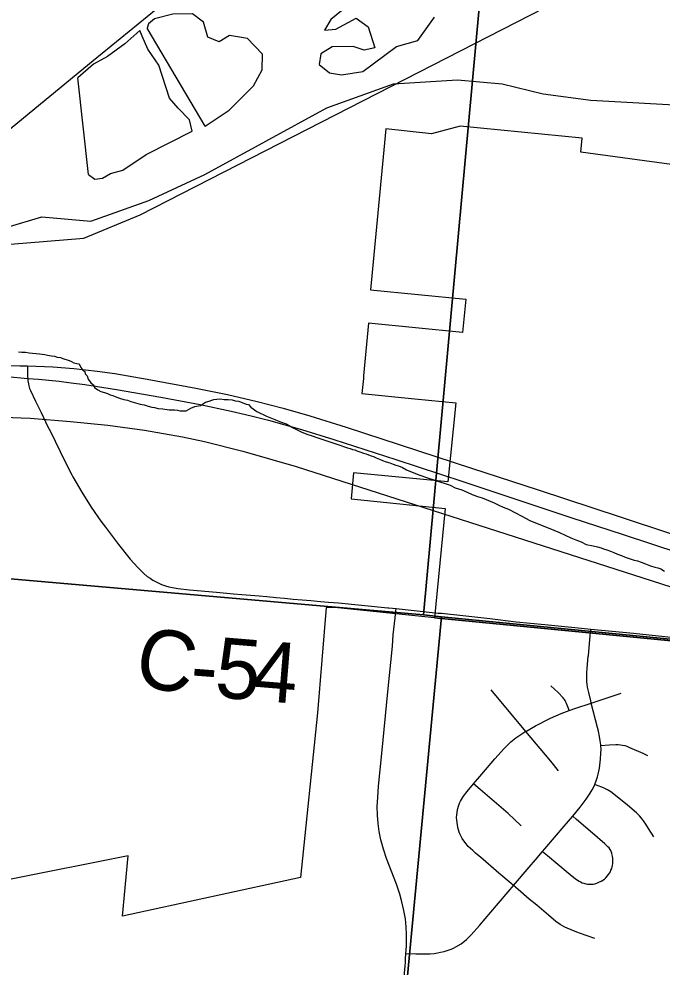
# Model space of a CAD drawing. Extents: x -1.4 to 35.4, y 0 to 22.
# Drawn here: x 25.196 to 25.802, y 15.521 to 16.414 of the extents above; entities that cross this region are included whole.
import ezdxf

# ---------------------------------------------------------------- set-up
doc = ezdxf.new("R2010")
doc.units = 0
for name, color, linetype in [('GM_X_County_Road', 7, 'Continuous'), ('GM_X_County_Road_Text', 7, 'Continuous'), ('GM_X_County_Text', 7, 'Continuous'), ('GM_X_Minor_Lake', 7, 'Continuous'), ('GM_X_Minor_River', 7, 'Continuous'), ('GM_X_Rail_Line', 7, 'Continuous'), ('GM_X_Section', 7, 'Continuous'), ('GM_X_State_Route', 7, 'Continuous'), ('GM_X_Township_Road', 7, 'Continuous')]:
    doc.layers.add(name, color=color, linetype=linetype)

msp = doc.modelspace()

# ---------------------------------------------------------------- linework, layer by layer
at = {"layer": 'GM_X_County_Road'}
for points in [[(25.20365, 16.08697), (25.20355, 16.08397), (25.20368, 16.07689), (25.20383, 16.07532)], [(25.20383, 16.07532), (25.20405, 16.07298), (25.20449, 16.07018), (25.20485, 16.06832), (25.2056, 16.06584), (25.20644, 16.06373), (25.2111, 16.05368), (25.21637, 16.04313), (25.22295, 16.02972), (25.22521, 16.0251)], [(25.22521, 16.0251), (25.23875, 15.99734), (25.2455, 15.9843)], [(25.2455, 15.9843), (25.24644, 15.98248), (25.25474, 15.96796), (25.26368, 15.95383), (25.2729, 15.94062), (25.27715, 15.93496)], [(25.27715, 15.93496), (25.28928, 15.91878), (25.30054, 15.90477), (25.30749, 15.8969), (25.31327, 15.89139), (25.31653, 15.8887), (25.3191, 15.88692), (25.32168, 15.88523), (25.32431, 15.88374), (25.32665, 15.88256), (25.32982, 15.88111), (25.33367, 15.87976), (25.33678, 15.87887), (25.34026, 15.87808), (25.34521, 15.87726), (25.35628, 15.87606), (25.38167, 15.87388), (25.39774, 15.87235), (25.40577, 15.87163), (25.4138, 15.87091), (25.42183, 15.87022), (25.42925, 15.86958), (25.43789, 15.86882), (25.44593, 15.86809), (25.45395, 15.86736), (25.4626, 15.86659), (25.47064, 15.8659), (25.47991, 15.86509), (25.48733, 15.86444), (25.4966, 15.86362), (25.54329, 15.85908)], [(25.54329, 15.85908), (25.5442, 15.85899), (25.55111, 15.85827)], [(25.55015, 15.84956), (25.55089, 15.85633), (25.55111, 15.85827)], [(25.55111, 15.85827), (25.59054, 15.85417), (25.59364, 15.85395), (25.61403, 15.85177), (25.63934, 15.84887), (25.66401, 15.84599), (25.69118, 15.8432), (25.72583, 15.83994), (25.73446, 15.83909)], [(25.5603, 15.53339), (25.56075, 15.54036), (25.56094, 15.55096), (25.56059, 15.55847), (25.55972, 15.56593), (25.55837, 15.57394), (25.55656, 15.58186), (25.55452, 15.58906), (25.55133, 15.59851), (25.54206, 15.62288), (25.53909, 15.63165), (25.5366, 15.64056), (25.53502, 15.64841), (25.53402, 15.65573), (25.53343, 15.66371), (25.53331, 15.67172), (25.53364, 15.68036), (25.5345, 15.69085), (25.53763, 15.72171), (25.54323, 15.77978), (25.54761, 15.82301), (25.54838, 15.83355), (25.55015, 15.84956)], [(25.73446, 15.83909), (25.77464, 15.8351), (25.80428, 15.83198), (25.82588, 15.8295), (25.84452, 15.82697), (25.84979, 15.82617), (25.86218, 15.82412), (25.8673, 15.82321), (25.87379, 15.82181), (25.87954, 15.82049), (25.88586, 15.81897), (25.89318, 15.81688)], [(25.53885, 15.29831), (25.54078, 15.31999), (25.54339, 15.34971), (25.54541, 15.37073), (25.55388, 15.46045), (25.55969, 15.52173), (25.55975, 15.52483), (25.55995, 15.52793), (25.5603, 15.53339)]]:
    msp.add_lwpolyline(points, dxfattribs=at)
at = {"layer": 'GM_X_County_Text'}
for points in [[(25.94903, 16.25792), (25.72505, 16.28855), (25.72628, 16.30175), (25.61133, 16.31284), (25.58444, 16.30585), (25.54144, 16.31044), (25.52704, 16.15887), (25.61682, 16.14984), (25.61374, 16.11863), (25.52506, 16.12738), (25.52196, 16.09419), (25.52042, 16.0776), (25.5202, 16.0753), (25.51887, 16.06103), (25.56873, 16.05608), (25.60721, 16.05228), (25.59985, 15.97784), (25.51077, 15.98632), (25.50853, 15.96168), (25.59738, 15.95277), (25.58718, 15.84949), (25.73939, 15.83491), (26.13662, 15.79613)], [(26.45501, 15.55992), (26.09418, 15.5213), (26.1119, 15.7121), (26.12869, 15.71539), (26.13662, 15.79613), (25.73939, 15.83491), (25.58719, 15.84949), (25.49604, 15.85897), (25.48524, 15.85929), (25.47708, 15.76014), (25.46096, 15.60505), (25.29309, 15.56851), (25.29849, 15.62549), (25.07154, 15.58016)]]:
    msp.add_lwpolyline(points, dxfattribs=at)
at = {"layer": 'GM_X_Minor_Lake'}
for points in [[(25.37105, 16.31291), (25.39374, 16.32803), (25.41658, 16.35112), (25.42485, 16.36615), (25.42515, 16.38095), (25.41103, 16.39568), (25.39401, 16.3983), (25.38441, 16.39242), (25.3735, 16.39682), (25.36961, 16.41095), (25.35914, 16.41876), (25.34055, 16.41838), (25.32339, 16.41417), (25.3176, 16.40934), (25.31638, 16.40519)], [(25.49956, 16.42161), (25.48954, 16.41346), (25.48364, 16.40332), (25.49428, 16.40425), (25.51346, 16.41487), (25.52468, 16.40667), (25.53111, 16.38678), (25.52082, 16.38471), (25.51065, 16.38796), (25.49091, 16.3876), (25.48016, 16.38098), (25.47844, 16.37114), (25.48815, 16.36334), (25.49949, 16.36121), (25.51966, 16.3646), (25.55124, 16.3879), (25.57146, 16.39356), (25.58707, 16.41566)], [(25.37105, 16.31291), (25.31638, 16.40519)], [(25.26126, 16.26728), (25.26724, 16.26298), (25.27447, 16.26397), (25.28176, 16.26838), (25.29359, 16.27156), (25.31551, 16.28631), (25.35882, 16.30823), (25.35638, 16.31891), (25.34559, 16.32977), (25.33744, 16.33943), (25.32744, 16.3704), (25.31712, 16.38542), (25.31168, 16.39769), (25.30951, 16.40305), (25.29522, 16.39042), (25.27905, 16.3786), (25.266, 16.37126), (25.25096, 16.35865)], [(25.26126, 16.26728), (25.25096, 16.35865)]]:
    msp.add_lwpolyline(points, dxfattribs=at)
at = {"layer": 'GM_X_Minor_River'}
for points in [[(25.18363, 16.21757), (25.21721, 16.22752), (25.26341, 16.22355), (25.31805, 16.24296), (25.37089, 16.26734), (25.48559, 16.33035), (25.54864, 16.353), (25.60903, 16.35671), (25.65106, 16.35282), (25.68956, 16.3433), (25.73459, 16.33745), (25.83046, 16.33208), (25.84447, 16.33066), (25.9464, 16.32516), (26.00204, 16.31871), (26.05844, 16.31262), (26.15296, 16.29664), (26.18177, 16.29567), (26.2226, 16.28876), (26.33585, 16.27999), (26.3975, 16.27075), (26.46407, 16.26103)], [(25.19523, 16.10041), (25.19826, 16.09998), (25.20167, 16.09992), (25.20508, 16.09949), (25.20849, 16.09905), (25.2119, 16.09862), (25.21494, 16.09857), (25.21759, 16.09815), (25.21986, 16.09773), (25.22251, 16.09731), (25.22629, 16.09648), (25.22894, 16.09606), (25.23159, 16.09526), (25.23462, 16.09483), (25.23689, 16.09403), (25.23877, 16.09324), (25.24104, 16.09283), (25.24293, 16.09204), (25.24519, 16.09124), (25.24745, 16.09006), (25.2501, 16.08926), (25.25237, 16.08884), (25.25383, 16.0854), (25.25569, 16.08309), (25.25757, 16.08192), (25.25792, 16.07964), (25.25978, 16.07771), (25.26087, 16.07465), (25.26347, 16.07119), (25.26572, 16.06925), (25.26682, 16.06657), (25.26983, 16.06463), (25.27284, 16.06306), (25.27623, 16.06186)], [(25.27623, 16.06186), (25.27888, 16.06106), (25.28152, 16.05988), (25.28416, 16.05907), (25.2868, 16.05789), (25.29133, 16.0563), (25.29436, 16.05549), (25.29776, 16.05467), (25.30116, 16.05348), (25.30531, 16.05227), (25.30985, 16.05106), (25.31363, 16.05024), (25.31741, 16.04904), (25.32081, 16.04822), (25.32347, 16.0478), (25.32687, 16.04698), (25.33104, 16.04654), (25.3371, 16.04568), (25.34013, 16.04563), (25.34203, 16.0456), (25.34506, 16.04517), (25.34733, 16.04475), (25.35037, 16.0447), (25.35303, 16.04466), (25.35762, 16.04724), (25.36144, 16.0487), (25.36487, 16.04941), (25.36677, 16.04976), (25.37138, 16.05272), (25.37481, 16.05381), (25.37749, 16.0549), (25.37939, 16.05525), (25.38205, 16.05559), (25.38547, 16.05591), (25.38888, 16.05548), (25.39268, 16.05541), (25.39647, 16.05498), (25.39949, 16.05417), (25.40252, 16.05374), (25.40441, 16.05333), (25.40969, 16.05096), (25.41196, 16.05054), (25.4142, 16.04823), (25.41983, 16.04396), (25.42887, 16.03963), (25.43679, 16.03646), (25.44283, 16.03409), (25.44736, 16.03249), (25.45037, 16.03092), (25.45338, 16.02898), (25.45715, 16.02702), (25.46167, 16.02504), (25.46695, 16.02268), (25.47186, 16.02108), (25.47639, 16.01948), (25.48772, 16.01588), (25.49225, 16.01429), (25.49603, 16.01309), (25.49904, 16.0119), (25.50244, 16.0107), (25.50508, 16.0099), (25.50773, 16.0091), (25.51, 16.0083), (25.51227, 16.00788), (25.51415, 16.00709), (25.51604, 16.0063), (25.51793, 16.00589), (25.52019, 16.00471), (25.52284, 16.00429), (25.5251, 16.00312), (25.52736, 16.00232), (25.52963, 16.00152), (25.53227, 16.00034), (25.53529, 15.99915), (25.5383, 15.99796), (25.5417, 15.99677), (25.5451, 15.99557), (25.54812, 15.99438), (25.55076, 15.99358), (25.55341, 15.99278), (25.55718, 15.9912), (25.56094, 15.98923), (25.56622, 15.98687), (25.57339, 15.98409), (25.58056, 15.9817), (25.58661, 15.9797), (25.59227, 15.97771), (25.59718, 15.97611), (25.60209, 15.97451), (25.60661, 15.97216), (25.61303, 15.97015), (25.61793, 15.96817), (25.62283, 15.96581), (25.62773, 15.96383), (25.63227, 15.96262), (25.63604, 15.96104), (25.63981, 15.95946), (25.64358, 15.95788), (25.64773, 15.95591), (25.65187, 15.95394), (25.65678, 15.95196)], [(25.65678, 15.95196), (25.66356, 15.94843), (25.66958, 15.9453), (25.67711, 15.94138), (25.69974, 15.93227), (25.70502, 15.9299), (25.7103, 15.92754), (25.71557, 15.92517), (25.72048, 15.92319), (25.72538, 15.92121), (25.73028, 15.91885), (25.73671, 15.91761), (25.74087, 15.9164), (25.74427, 15.91559), (25.74654, 15.91479), (25.74956, 15.9136), (25.75296, 15.91241), (25.75635, 15.91121), (25.75974, 15.90963), (25.76352, 15.90843), (25.76691, 15.90686), (25.77069, 15.90566), (25.77522, 15.90406), (25.77862, 15.90325), (25.78202, 15.90206), (25.78617, 15.90047), (25.7907, 15.89849), (25.79485, 15.89728), (25.79751, 15.89686), (25.80052, 15.89567), (25.80391, 15.89372)]]:
    msp.add_lwpolyline(points, dxfattribs=at)
at = {"layer": 'GM_X_Rail_Line'}
for points in [[(24.57077, 15.89869), (24.59778, 15.91683), (24.64241, 15.95119), (24.68704, 15.98297), (24.73167, 16.01304), (24.86298, 16.08434), (25.02005, 16.1797), (25.14793, 16.2785), (25.26552, 16.37473), (25.34191, 16.43745), (25.65784, 16.80861), (26.05272, 17.30643), (27.88065, 19.16783), (28.37806, 19.63652)], [(24.57021, 15.89009), (24.57642, 15.89374), (24.58531, 15.90052), (24.5864, 15.90135), (24.65923, 15.95688), (24.75584, 16.01806), (24.90765, 16.10292), (25.02989, 16.17594), (25.1403, 16.20161), (25.18762, 16.20161), (25.25662, 16.20754), (25.30986, 16.22926), (26.5579, 16.86871), (27.49441, 17.30294), (28.05694, 17.52298)], [(25.16419, 16.03927), (25.20626, 16.03786), (25.24413, 16.03459), (25.27943, 16.03109), (25.31403, 16.02641), (25.34956, 16.0201), (25.37037, 16.01566), (25.4066, 16.00677), (25.45686, 15.99228), (25.96435, 15.82935), (26.24674, 15.73865), (26.2846, 15.72649), (26.3199, 15.71527), (26.34795, 15.70639), (26.37928, 15.69727), (26.40686, 15.68956), (26.43959, 15.68231), (26.47161, 15.67577)]]:
    msp.add_lwpolyline(points, dxfattribs=at)
at = {"layer": 'GM_X_Section'}
for points in [[(25.66845, 16.85281), (25.57689, 15.85237), (24.57444, 15.93982), (24.56244, 15.94109), (24.65726, 16.95816)], [(26.64566, 16.75445), (26.54696, 15.75756), (25.5939, 15.85057), (25.57689, 15.85237), (25.66845, 16.85281)], [(24.57444, 15.93982), (25.57689, 15.85237), (25.5939, 15.85057), (25.49799, 14.83922), (24.49302, 14.93411)], [(25.5939, 15.85057), (26.54696, 15.75756), (26.56663, 15.75608), (26.47381, 14.7481), (25.49799, 14.83922)]]:
    msp.add_lwpolyline(points, close=True, dxfattribs=at)
at = {"layer": 'GM_X_State_Route'}
for points in [[(25.17158, 16.0874), (25.1964, 16.08722), (25.20365, 16.08697), (25.2274, 16.08615), (25.24719, 16.08462), (25.26938, 16.08217), (25.28596, 16.07979), (25.31656, 16.07457), (25.36236, 16.06612), (25.39216, 16.05999), (25.42, 16.05361), (25.44465, 16.04731), (25.46972, 16.04014), (25.50407, 16.02933), (25.62216, 15.99067), (25.68474, 15.97014), (25.76204, 15.94465), (25.85886, 15.91289)], [(25.18764, 16.07661), (25.2006, 16.07558), (25.20383, 16.07532), (25.2139, 16.07454), (25.23352, 16.07265), (25.24495, 16.07119), (25.25782, 16.06943), (25.2876, 16.06484), (25.32926, 16.0577), (25.36651, 16.05054), (25.39572, 16.04439), (25.41448, 16.03997), (25.43075, 16.03576), (25.4619, 16.02709), (25.49223, 16.01782), (25.55075, 15.99878), (25.61392, 15.97801), (25.71577, 15.9443), (25.76513, 15.92809), (25.89674, 15.88468), (25.96232, 15.86325), (26.15303, 15.80055), (26.23697, 15.77292)]]:
    msp.add_lwpolyline(points, dxfattribs=at)
at = {"layer": 'GM_X_Township_Road'}
for points in [[(25.73222, 15.81419), (25.73387, 15.83255), (25.73446, 15.83909)], [(25.73494, 15.76924), (25.73437, 15.77141), (25.7325, 15.77912), (25.73196, 15.78179), (25.73141, 15.78442), (25.73099, 15.7869), (25.73079, 15.78961), (25.73068, 15.79245), (25.73071, 15.79486), (25.73088, 15.79793), (25.7312, 15.80225), (25.73214, 15.81332), (25.73222, 15.81419)], [(25.67322, 15.74263), (25.66894, 15.74781), (25.64826, 15.7728), (25.64064, 15.78181)], [(25.71418, 15.76218), (25.71346, 15.76409), (25.71162, 15.76893), (25.71111, 15.77026), (25.71037, 15.77163), (25.70974, 15.77257), (25.70919, 15.77327), (25.70831, 15.77419), (25.70359, 15.77912), (25.69669, 15.78542)], [(25.73494, 15.76924), (25.74894, 15.77384), (25.76302, 15.77858)], [(25.67322, 15.74263), (25.68251, 15.74794), (25.69636, 15.75498), (25.70664, 15.75939), (25.71418, 15.76218)], [(25.71418, 15.76218), (25.71946, 15.76414), (25.73494, 15.76924)], [(25.7439, 15.72938), (25.74385, 15.73006), (25.74336, 15.73379), (25.74268, 15.73794), (25.74164, 15.74295), (25.74095, 15.74621), (25.73494, 15.76924)], [(25.62407, 15.69314), (25.63176, 15.70215), (25.6442, 15.71675), (25.65289, 15.72644), (25.65907, 15.73262), (25.6639, 15.73662), (25.67225, 15.74208), (25.67322, 15.74263)], [(25.70409, 15.70547), (25.69675, 15.71467), (25.67322, 15.74263)], [(25.73823, 15.69265), (25.7386, 15.69348), (25.73985, 15.69687), (25.74074, 15.69964), (25.74147, 15.70227), (25.74213, 15.7051), (25.74259, 15.7078), (25.74375, 15.71647), (25.7441, 15.72208), (25.74413, 15.72564), (25.7439, 15.72938)], [(25.7439, 15.72938), (25.75182, 15.72987), (25.75797, 15.73025), (25.7603, 15.73021), (25.76241, 15.73002), (25.76438, 15.72973), (25.76648, 15.72921), (25.76843, 15.72861), (25.77112, 15.72758), (25.78347, 15.72198), (25.78806, 15.72004)], [(25.66163, 15.59735), (25.65956, 15.59911), (25.64778, 15.60913), (25.63044, 15.62395), (25.62765, 15.62632), (25.62582, 15.62792), (25.62318, 15.63039), (25.61908, 15.63418), (25.6169, 15.63664), (25.61486, 15.63934), (25.61328, 15.64171), (25.61189, 15.64421), (25.6111, 15.64593), (25.61051, 15.64764), (25.60986, 15.64988), (25.60926, 15.65218), (25.6088, 15.65456), (25.60847, 15.65666), (25.60821, 15.65884), (25.60807, 15.66134), (25.60821, 15.66385), (25.60847, 15.66615), (25.609, 15.66892), (25.61019, 15.6732), (25.61084, 15.67498), (25.6117, 15.67671), (25.61462, 15.68161), (25.61808, 15.68611), (25.62407, 15.69314)], [(25.66893, 15.65376), (25.65655, 15.66511), (25.64343, 15.67658), (25.63021, 15.68789), (25.62407, 15.69314)], [(25.71746, 15.66283), (25.72452, 15.67117), (25.73025, 15.67858), (25.73402, 15.68435), (25.73576, 15.6874), (25.73725, 15.69044), (25.73823, 15.69265)], [(25.79389, 15.64316), (25.78901, 15.65106), (25.78631, 15.65528), (25.78426, 15.65837), (25.78236, 15.6607), (25.78034, 15.6629), (25.77745, 15.66585), (25.76894, 15.67319), (25.75629, 15.68335), (25.75325, 15.68559), (25.75022, 15.68753), (25.74774, 15.68874), (25.74497, 15.68997), (25.74129, 15.69137), (25.73823, 15.69265)], [(25.68912, 15.62953), (25.6912, 15.63196), (25.70931, 15.6532), (25.71746, 15.66283)], [(25.68912, 15.62953), (25.69381, 15.62558), (25.71327, 15.60923), (25.7185, 15.60483), (25.72102, 15.60301), (25.72359, 15.60131), (25.72468, 15.60074), (25.72636, 15.59994), (25.72787, 15.59947), (25.72993, 15.59893), (25.73153, 15.59871), (25.73362, 15.59854), (25.73495, 15.59855), (25.73678, 15.59875), (25.73837, 15.59903), (25.74031, 15.59968), (25.74211, 15.60042), (25.74427, 15.60143), (25.74569, 15.60225), (25.74738, 15.60347), (25.74864, 15.6046), (25.75005, 15.60606), (25.75123, 15.60763), (25.7522, 15.60909), (25.75294, 15.61037), (25.75353, 15.61176), (25.75421, 15.61335), (25.75473, 15.61515), (25.75504, 15.61634), (25.75532, 15.6181), (25.75541, 15.61969), (25.75541, 15.62152), (25.75525, 15.62326), (25.75509, 15.62458), (25.75477, 15.62609), (25.75437, 15.62773), (25.75376, 15.62929), (25.75326, 15.63039), (25.75263, 15.63144), (25.75166, 15.63274), (25.75066, 15.63383), (25.74784, 15.6366), (25.73606, 15.64654), (25.72114, 15.65961), (25.71746, 15.66283)], [(25.66163, 15.59735), (25.67626, 15.61452), (25.68233, 15.62158), (25.68912, 15.62953)], [(25.5603, 15.53339), (25.56945, 15.53312), (25.57651, 15.53291), (25.58326, 15.53297), (25.58674, 15.53333), (25.59013, 15.53386), (25.59289, 15.53443), (25.59625, 15.5353), (25.59912, 15.53616), (25.60281, 15.53742), (25.60513, 15.53844), (25.60739, 15.53954), (25.61225, 15.5425), (25.61721, 15.54641), (25.62172, 15.55081), (25.62947, 15.55977), (25.64565, 15.57862), (25.65855, 15.59374), (25.66163, 15.59735)], [(25.73835, 15.54738), (25.72384, 15.55254), (25.72213, 15.55318), (25.71813, 15.5547), (25.71003, 15.55798), (25.70567, 15.56053), (25.70156, 15.56341), (25.69454, 15.56955), (25.68374, 15.57882), (25.67653, 15.58465), (25.66614, 15.59353), (25.66163, 15.59735)]]:
    msp.add_lwpolyline(points, dxfattribs=at)

# ---------------------------------------------------------------- texts
at = {"layer": 'GM_X_County_Road_Text'}
for s, rotation, p in [('C', 348.07235, (25.30213, 15.78759)), ('5', 355.22253, (25.37908, 15.77503)), ('4', 355.33419, (25.41408, 15.7721)), ('-', 355.6737, (25.35594, 15.77678))]:
    msp.add_text(s, height=0.05682, rotation=rotation, dxfattribs=at).set_placement(p)

doc.saveas('drawing.dxf')
